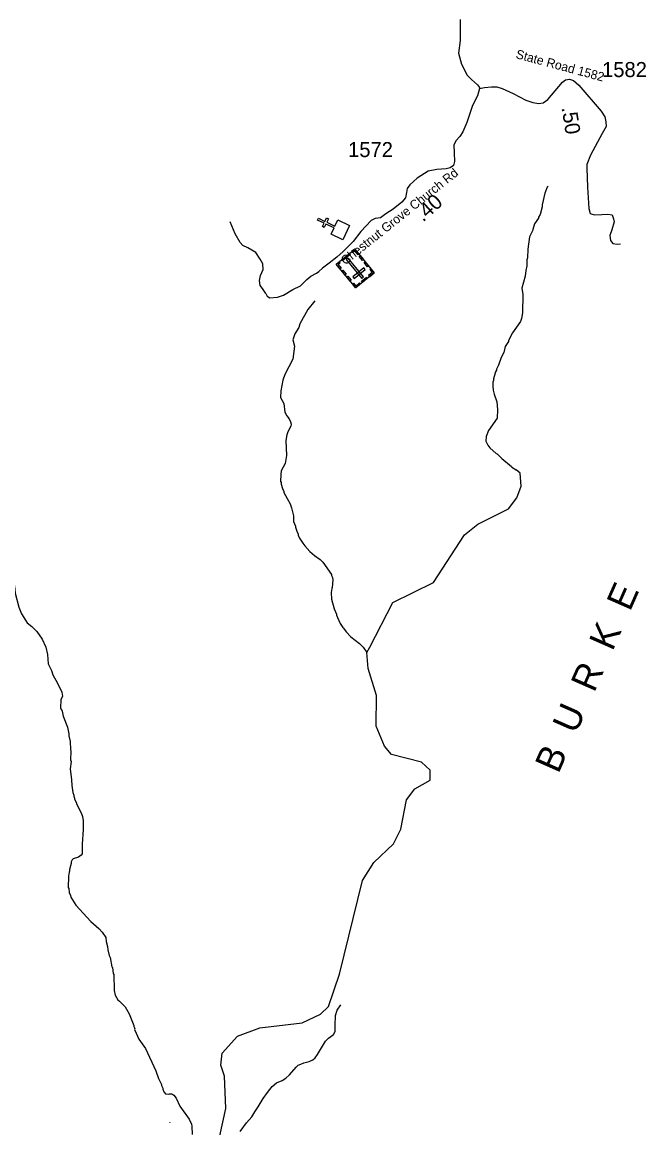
# Model space of a CAD drawing. Extents: x 1248089 to 1457196, y 820910 to 988753.
# Drawn here: x 1336533 to 1341708, y 919465 to 928641 of the extents above; entities that cross this region are included whole.
import ezdxf

# ---------------------------------------------------------------- set-up
doc = ezdxf.new("R2010")
doc.units = 0
for name, color, linetype in [('Exist Cultural Cemetery CELL', 7, 'Continuous'), ('Exist Cultural Church CELL', 7, 'Continuous'), ('Exist Geographical Mountain Summit Label', 7, 'Continuous'), ('Exist Hydrographic Creek Single Shore', 7, 'Continuous'), ('Exist Hydrographic Misc Water Feature', 7, 'Continuous'), ('Exist Road Non-System Type 51', 7, 'Continuous'), ('Exist Road Secondary Type 41 Attributed', 7, 'Continuous'), ('Exist Road Secondary Type 51 Attributed', 7, 'Continuous'), ('Exist Road Secondary Type 51 Label', 7, 'Continuous'), ('Prop GRAU CAT1 Cell', 7, 'Continuous'), ('Prop Lane Lines', 7, 'Continuous')]:
    doc.layers.add(name, color=color, linetype=linetype)

msp = doc.modelspace()

# ---------------------------------------------------------------- linework, layer by layer
at = {"layer": 'Exist Cultural Cemetery CELL'}
for points in [[(1339454.3, 926561.5), (1339300.5, 926435.1), (1339138.8, 926631.9), (1339292.7, 926758.2)], [(1339255.6, 926712.9), (1339190, 926659), (1339182.7, 926667.8), (1339248.3, 926721.7)], [(1339267.1, 926737.2), (1339274.4, 926728.3), (1339291.4, 926742.3), (1339317.1, 926711.1), (1339325.7, 926718.1), (1339292.7, 926758.2)], [(1339337.1, 926704.2), (1339364.6, 926670.7), (1339355.8, 926663.5), (1339328.3, 926697)], [(1339164.4, 926652.9), (1339171.7, 926644), (1339154.7, 926630.1), (1339180.4, 926598.8), (1339171.8, 926591.8), (1339138.8, 926631.9)], [(1339351.5, 926514.9), (1339365.9, 926526.8), (1339237.2, 926683.5), (1339222.7, 926671.6)], [(1339379.7, 926652.3), (1339407.2, 926618.8), (1339398.4, 926611.6), (1339370.9, 926645)], [(1339193.5, 926583.2), (1339221, 926549.8), (1339212.2, 926542.5), (1339184.7, 926576)], [(1339235.3, 926532.3), (1339262.8, 926498.8), (1339254, 926491.6), (1339226.5, 926525.1)], [(1339379.6, 926588.2), (1339367.7, 926602.6), (1339276.7, 926527.9), (1339288.6, 926513.4)], [(1339397.1, 926514.5), (1339357, 926481.6), (1339349.8, 926490.4), (1339389.8, 926523.3)], [(1339426.8, 926595), (1339418, 926587.7), (1339438.5, 926562.9), (1339407.1, 926537.1), (1339414.2, 926528.5), (1339454.3, 926561.5)], [(1339272.9, 926468.6), (1339281.7, 926475.8), (1339302.1, 926450.9), (1339333.4, 926476.7), (1339340.5, 926468.1), (1339300.4, 926435.1)]]:
    msp.add_lwpolyline(points, close=True, dxfattribs=at)
at = {"layer": 'Exist Cultural Church CELL'}
msp.add_lwpolyline([(1339097.2, 926881.5), (1339121.7, 926932.9), (1339053, 926965.7), (1339039.2, 926936.8), (1339024.8, 926943.7), (1339038.6, 926972.6), (1338984.3, 926998.5), (1338991.2, 927013), (1339045.5, 926987.1), (1339059.3, 927015.9), (1339073.7, 927009), (1339059.9, 926980.2), (1339128.6, 926947.3), (1339153.6, 926999.3), (1339249.6, 926953.4), (1339193.3, 926835.5)], close=True, dxfattribs=at)
at = {"layer": 'Exist Hydrographic Creek Single Shore'}
msp.add_lwpolyline([(1338149.2, 919286.8), (1338223.2, 919626.7), (1338212.1, 919892.9), (1338181.2, 919985.4), (1338192.1, 920083.7), (1338320.2, 920225.6), (1338505.2, 920294.1), (1338856.2, 920336.3), (1339008.3, 920408.8), (1339076.2, 920473), (1339165.2, 920740.4), (1339357.2, 921517.9), (1339452.2, 921667), (1339614.2, 921821.4), (1339675.2, 921944.8), (1339722.2, 922186.9), (1339791.2, 922277.4), (1339918.2, 922350.3), (1339919.2, 922432.4), (1339846.2, 922499.5), (1339597.2, 922563.6), (1339540.2, 922633.7), (1339469.2, 922799.3), (1339474.2, 923052), (1339404.2, 923276.6), (1339392.7, 923410.2), (1339417.2, 923453.6), (1339608.2, 923824), (1339945.2, 923991.2), (1340204.2, 924386.6), (1340315.2, 924476.3), (1340568.2, 924602.5), (1340636.2, 924693), (1340672.2, 924790.8), (1340666.2, 924899.3), (1340633.2, 924926.2)], dxfattribs=at)
at = {"layer": 'Exist Hydrographic Misc Water Feature'}
for points in [[(1340896.6, 927280.1), (1340888.8, 927270.1), (1340869.7, 927220.5), (1340847.5, 927125), (1340847.2, 927109), (1340829.8, 927045.4), (1340817.3, 927021.7), (1340817.2, 927013.7), (1340784.1, 926966.5), (1340770.1, 926921.1), (1340771, 926914.8), (1340741.8, 926859.4), (1340727.6, 926757.7), (1340725.9, 926683.8), (1340721.6, 926667.9), (1340720.6, 926619.9), (1340711.7, 926580.2), (1340706.7, 926532.3), (1340679.1, 926434), (1340687.4, 926380.7), (1340684.1, 926228.8), (1340675.1, 926181), (1340666.6, 926157.2), (1340600.5, 926062.7), (1340567.1, 925999.5), (1340566.9, 925991.5), (1340542, 925948.1), (1340529, 925900.4), (1340508, 925856.8), (1340486.6, 925793.4), (1340469.9, 925761.7), (1340469.7, 925753.7), (1340461.4, 925737.9), (1340444.2, 925682.3), (1340443.9, 925666.3), (1340439.6, 925652.4), (1340438.9, 925618.5), (1340442.2, 925586.4), (1340449.4, 925554.2), (1340472.8, 925490.8), (1340476.3, 925425.3), (1340473.1, 925353.7), (1340402.9, 925251.3), (1340381.8, 925203.7), (1340380.9, 925163.9), (1340396.2, 925131.5), (1340413.8, 925107.1), (1340464.7, 925062), (1340474.7, 925059.7), (1340513.8, 925020.8), (1340594, 924952.7), (1340596.2, 924947), (1340633.2, 924926.2)], [(1338962.3, 926327.4), (1338904.7, 926256.8), (1338838.1, 926138.3), (1338829.4, 926106.5), (1338796.7, 926055.2), (1338779.2, 926003.7), (1338794, 925951.3), (1338779.7, 925843.6), (1338712.9, 925717.2), (1338695.9, 925669.5), (1338681, 925581.6), (1338676.9, 925526), (1338703.7, 925477.4), (1338714.2, 925405.2), (1338729.5, 925372.8), (1338748.9, 925348.4), (1338760.4, 925324.1), (1338764, 925304.1), (1338763.7, 925288.1), (1338738.6, 925240.7), (1338730.1, 925216.9), (1338721, 925169.1), (1338726.4, 925044.9), (1338716.9, 924977.2), (1338683.6, 924917.9), (1338678.9, 924886), (1338677.7, 924830.1), (1338681.6, 924822), (1338681.3, 924808), (1338692.3, 924769.8), (1338703.8, 924745.6), (1338703.7, 924737.6), (1338731, 924686.8), (1338757.4, 924643.5), (1338768, 924611.8), (1338784.6, 924544.8), (1338784.2, 924497), (1338801.6, 924459.4), (1338801.4, 924451.4), (1338812.7, 924417.2), (1338824.2, 924390.9), (1338824, 924382.9), (1338835.5, 924358.6), (1338863.1, 924317.7)], [(1336098.8, 924907.1), (1336084.9, 924734.9), (1336121.4, 924586.5), (1336157.2, 924489.8), (1336180, 924436.8), (1336226, 924351.3), (1336280, 924266.5), (1336340.4, 924193.1), (1336375.1, 924135.8), (1336448.7, 924030.1), (1336469.2, 923961.5), (1336475.8, 923901.5), (1336505, 923785.1), (1336527.8, 923732.1), (1336576, 923654.8), (1336615.4, 923626.2), (1336654.5, 923583.6), (1336701, 923521.8), (1336729.5, 923453.1), (1336744.1, 923393), (1336750.3, 923314.8), (1336776.8, 923260.6), (1336787.6, 923224.5), (1336827.8, 923155.9)], [(1338863.1, 924317.7), (1338878.1, 924295.7), (1338921, 924246.8), (1338960.3, 924213.9), (1339005.7, 924182.9), (1339029.1, 924158.4), (1339100.9, 924056.8), (1339100.7, 924048.8), (1339108.4, 924032.6), (1339111.9, 924012.5), (1339106.5, 923948.6), (1339102.3, 923940.7), (1339097.6, 923908.8), (1339100.5, 923852.8), (1339122.7, 923772.3), (1339141.7, 923727.9), (1339141.6, 923719.9), (1339149.1, 923699.7), (1339172.1, 923651.2), (1339193.3, 923616.7), (1339199.2, 923612.6), (1339220.6, 923582.2), (1339261.7, 923539.2), (1339332.5, 923485.6), (1339361.8, 923455), (1339392.7, 923410.2)], [(1336827.8, 923155.9), (1336863.8, 923079.7), (1336867.2, 923047.7), (1336854.5, 923016), (1336853, 922952), (1336856.7, 922935.9), (1336860.7, 922935.8), (1336864.4, 922923.7), (1336872.6, 922882.8), (1336909.5, 922790.7), (1336920.3, 922734.5), (1336920, 922718.5), (1336931, 922670.3), (1336933.5, 922606.2), (1336937.2, 922590.2), (1336935.7, 922520.2), (1336939.4, 922506.1), (1336932.6, 922443.4), (1336944.1, 922354.1), (1336945, 922306), (1336953.7, 922247.8), (1336961.3, 922225.7), (1336961.1, 922217.7), (1336968.8, 922201.5), (1336968.6, 922193.5), (1336983.9, 922161.2), (1336983.7, 922153.2), (1337022.1, 922080.3), (1337033.4, 922048.1), (1337040.7, 922011.9), (1337040.4, 921940), (1337032.5, 921820.1), (1337032, 921795.5)], [(1337032, 921795.5), (1337030.7, 921740.2), (1337024.5, 921728.3), (1337002.1, 921710.8), (1336955.8, 921697.9), (1336947.7, 921690.1), (1336941.3, 921674.2), (1336940.9, 921658.2), (1336927.9, 921610.5), (1336927.6, 921594.6), (1336923.4, 921586.7), (1336918.7, 921554.8), (1336916.6, 921458.8), (1336920.4, 921450.7), (1336923.8, 921418.6), (1336935.2, 921394.4), (1336938.9, 921378.3), (1336979.5, 921313.4), (1337102.5, 921176.7), (1337169.2, 921119.2), (1337198.6, 921088.6), (1337227.6, 921043.9), (1337230.9, 921011.9), (1337242, 920971.6), (1337245.4, 920943.5), (1337256.4, 920895.3), (1337264, 920879.1), (1337278.3, 920802.8), (1337282.2, 920794.7), (1337289.1, 920746.6), (1337293, 920738.5), (1337298, 920604.5), (1337305.2, 920566.3), (1337328.4, 920527.8), (1337342.2, 920517.4), (1337389.1, 920468.4), (1337421.9, 920411.7), (1337459.8, 920314.8), (1337459.6, 920306.8), (1337467.2, 920290.7), (1337467.1, 920282.7), (1337478.4, 920250.4), (1337501.3, 920201.9), (1337555.7, 920124.7), (1337643.5, 919938.8), (1337666.2, 919874.3), (1337689.1, 919825.8), (1337688.9, 919817.8), (1337700.4, 919793.6), (1337700.2, 919785.6), (1337709.8, 919763.3), (1337723.4, 919747), (1337747.4, 919744.5), (1337755.5, 919748.4), (1337775.4, 919747.9), (1337793.1, 919735.4), (1337810.6, 919711), (1337841.2, 919646.5), (1337918.8, 919536.7), (1337938, 919496.3), (1337941.6, 919480.2), (1337944.1, 919410.1)]]:
    msp.add_lwpolyline(points, dxfattribs=at)
at = {"layer": 'Exist Road Non-System Type 51'}
for points in [[(1338554.2, 926390.3), (1338527.8, 926429.8), (1338508.1, 926456.2), (1338501.5, 926497.9), (1338510.3, 926539.6), (1338532.2, 926587.8), (1338530, 926633.9), (1338508.1, 926673.4), (1338473, 926728.3), (1338407.2, 926767.8), (1338365.5, 926787.6), (1338341.4, 926811.7), (1338301.9, 926884.2), (1338258.1, 926985.1)], [(1338554.2, 926390.3), (1338567.3, 926366.2), (1338587.1, 926353), (1338652.9, 926359.6), (1338701.1, 926374.9), (1338780.1, 926421), (1338841.5, 926454), (1338896.3, 926504.4), (1338929.2, 926533), (1338975.3, 926557.1), (1338995, 926570.3), (1339025.3, 926600.1)], [(1338341.3, 919434.8), (1338394, 919507.2), (1338437.9, 919555.5), (1338464.2, 919599.4), (1338492.7, 919641.1), (1338534.4, 919709.1), (1338569.4, 919757.4), (1338606.7, 919807.9), (1338644, 919838.6), (1338691.8, 919857.1), (1338722.5, 919876.8), (1338751, 919905.4), (1338808, 919969), (1338823.4, 919984.4), (1338845.3, 919993.2), (1338871.6, 920004.1), (1338915.5, 920017.3), (1338944, 920030.5), (1338963.8, 920045.8), (1338983.5, 920074.4), (1339051.5, 920184.1), (1339075.6, 920210.4), (1339093.2, 920223.6), (1339117.3, 920241.2), (1339130.4, 920265.3), (1339130.4, 920315.8), (1339132.6, 920397), (1339148, 920440.9), (1339178.7, 920487)], [(1337758.3, 919508.2), (1337757.8, 919509), (1337759.7, 919507), (1337758.3, 919508.2)]]:
    msp.add_lwpolyline(points, dxfattribs=at)
at = {"layer": 'Exist Road Secondary Type 41 Attributed'}
msp.add_lwpolyline([(1340328.7, 928089.2), (1340369.7, 928098.3), (1340426.4, 928104.6), (1340472.5, 928104.6), (1340514.5, 928089.9), (1340606.9, 928047.8), (1340711.8, 927993.2), (1340770.6, 927974.3), (1340818.8, 927965.9), (1340854.5, 927972.2), (1340894.4, 927999.5), (1340955.3, 928070.9), (1341016.1, 928142.4), (1341041.3, 928163.4), (1341074.9, 928167.6), (1341108.5, 928157.1), (1341152.5, 928117.2), (1341337.2, 927900.8), (1341368.7, 927854.6), (1341375, 927814.7), (1341377.1, 927774.8), (1341345.6, 927715.9), (1341249.1, 927537.4), (1341217.5, 927460.7), (1341217.5, 927429.2), (1341223.8, 927271.7), (1341234.3, 927093.1), (1341246.9, 927053.2), (1341280.5, 927040.6), (1341343.5, 927044.8), (1341391.7, 927046.9), (1341429.5, 927042.7), (1341439.2, 927007.7), (1341445.5, 926982.5), (1341424.5, 926917.4), (1341409.8, 926871.2), (1341414, 926829.2), (1341432.9, 926804), (1341470.7, 926797.7), (1341497.5, 926800.8)], dxfattribs=at)
at = {"layer": 'Exist Road Secondary Type 51 Attributed'}
for points in [[(1340167.5, 928662.5), (1340167.5, 928489.4), (1340152.9, 928384.3)], [(1340152.9, 928384.3), (1340178, 928291.9), (1340224.2, 928201.6), (1340262, 928163.8), (1340312.4, 928119.7), (1340326.6, 928099.7), (1340328.7, 928089.2)], [(1340328.7, 928089.2), (1340312.3, 928029.8), (1340268.3, 927947.9), (1340249.4, 927891.2), (1340222.1, 927807.2), (1340190.6, 927731.6), (1340163.3, 927691.7), (1340131.8, 927655.9), (1340115.1, 927620.2), (1340117.2, 927557.2), (1340121.4, 927485.8), (1340110.9, 927452.2), (1340083.6, 927433.3), (1340052.1, 927422.8), (1339974.4, 927418.6), (1339901, 927403.9), (1339811.9, 927346.6), (1339751, 927292), (1339728, 927260.4), (1339721.7, 927226.8), (1339713.3, 927182.7), (1339683.9, 927147), (1339610.4, 927088.2), (1339549.6, 927050.4), (1339505.5, 927016.8), (1339463.5, 927010.5), (1339429.9, 926993.7), (1339343.9, 926903.3), (1339278.8, 926819.3), (1339197.3, 926736.7), (1339144.9, 926690.5), (1339079.8, 926640.1), (1339025.3, 926600.1)]]:
    msp.add_lwpolyline(points, dxfattribs=at)

# ---------------------------------------------------------------- texts
at = {"layer": 'Exist Geographical Mountain Summit Label'}
msp.add_text('B  U  R  K  E', height=220, rotation=66.19157, dxfattribs=at).set_placement((1340982, 922397.5))
at = {"layer": 'Exist Road Secondary Type 51 Label'}
for s, rotation, p in [('State Road 1582', 344.89901, (1340623.7, 928343.2)), ('Chestnut Grove Church Rd', 38.65352, (1339214.5, 926620.9))]:
    msp.add_text(s, height=75, rotation=rotation, dxfattribs=at).set_placement(p)
at = {"layer": 'Prop GRAU CAT1 Cell'}
for s, rotation, p in [('.50', 278.96458, (1341008.2, 927931.6)), ('.40', 41.90289, (1339859.6, 926977.7))]:
    msp.add_text(s, height=125, rotation=rotation, dxfattribs=at).set_placement(p)
at = {"layer": 'Prop Lane Lines'}
for s, p in [('1582', (1341344.5, 928184.9)), ('1572', (1339237.5, 927520.8))]:
    msp.add_text(s, height=125, dxfattribs=at).set_placement(p)

doc.saveas('drawing.dxf')
